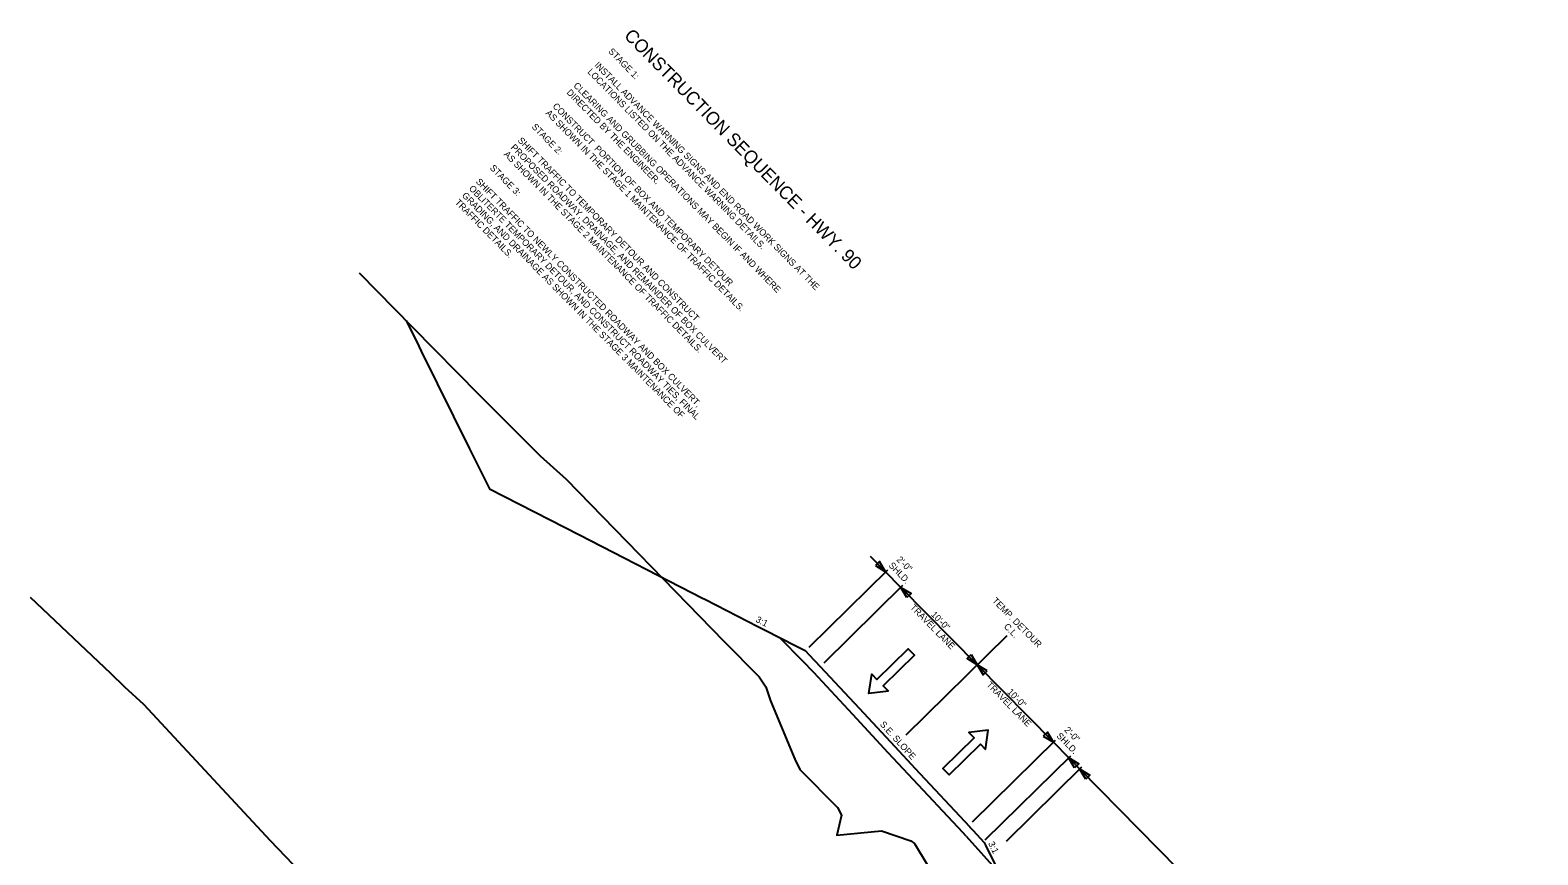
# Model space of a CAD drawing. Extents: x 1660188 to 1660468, y 670370 to 670621.
# Drawn here: x 1660307.3 to 1660446, y 670474.4 to 670550.3 of the extents above; entities that cross this region are included whole.
import ezdxf

# ---------------------------------------------------------------- set-up
doc = ezdxf.new("R2010")
doc.units = 0
for name, color, linetype in [('Default', 7, 'Continuous'), ('R_Annotation', 7, 'Continuous'), ('R_Dimension', 7, 'Continuous'), ('R_Exist Surface', 7, 'Continuous'), ('R_Horz Alg', 7, 'Continuous'), ('R_MOT', 7, 'Continuous')]:
    doc.layers.add(name, color=color, linetype=linetype)

msp = doc.modelspace()

# ---------------------------------------------------------------- linework, layer by layer
at = {"layer": 'Default'}
for points in [[(1660386.24, 670489.44), (1660384.45, 670489.22), (1660384.7, 670491), (1660385.18, 670490.51), (1660388.06, 670493.35), (1660388.64, 670492.76), (1660385.76, 670489.93)], [(1660395.18, 670484.09), (1660395.43, 670485.87), (1660393.64, 670485.65), (1660394.12, 670485.16), (1660391.24, 670482.32), (1660391.82, 670481.74), (1660394.7, 670484.58)]]:
    msp.add_lwpolyline(points, close=True, dxfattribs=at)
at = {"layer": 'R_Dimension'}
for p, q in [((1660378.95, 670493.51), (1660386.17, 670500.61)), ((1660385.98, 670500.43), (1660384.58, 670501.85)), ((1660380.34, 670492.06), (1660387.57, 670499.19)), ((1660387.39, 670499), (1660385.98, 670500.43)), ((1660387.39, 670499), (1660394.4, 670491.88)), ((1660401.42, 670484.75), (1660394.4, 670491.88)), ((1660393.98, 670477.43), (1660401.61, 670484.94)), ((1660401.42, 670484.75), (1660402.82, 670483.33)), ((1660395.15, 670475.77), (1660403.01, 670483.51)), ((1660397.09, 670475.66), (1660404.02, 670482.48)), ((1660402.82, 670483.33), (1660404.23, 670481.9)), ((1660403.83, 670482.3), (1660446, 670439.48))]:
    msp.add_line(p, q, dxfattribs=at)
for points in [[(1660385.05, 670501), (1660385.98, 670500.43), (1660385.43, 670501.37)], [(1660387.94, 670498.07), (1660387.39, 670499), (1660388.32, 670498.44)], [(1660393.85, 670492.82), (1660394.4, 670491.88), (1660393.47, 670492.45)], [(1660395.33, 670491.31), (1660394.4, 670491.88), (1660394.96, 670490.94)], [(1660400.49, 670485.32), (1660401.42, 670484.75), (1660400.87, 670485.69)], [(1660403.37, 670482.39), (1660402.82, 670483.33), (1660403.75, 670482.76)], [(1660404.39, 670481.36), (1660403.83, 670482.3), (1660404.76, 670481.73)]]:
    msp.add_lwpolyline(points, close=True, dxfattribs=at)
at = {"layer": 'R_Exist Surface'}
for points in [[(1660337.55, 670527.94), (1660342.45, 670522.95), (1660348.56, 670516.75), (1660354.2, 670511.1), (1660356.58, 670508.95), (1660371.1, 670494.06), (1660374.33, 670490.78), (1660374.95, 670489.86), (1660375.4, 670488.55), (1660377.62, 670483.18), (1660378.09, 670482.25), (1660381.55, 670478.74), (1660381.91, 670478.03), (1660381.49, 670476.19), (1660385.61, 670476.61), (1660388.29, 670475.69), (1660388.64, 670475.44), (1660389.79, 670473.5)], [(1660307.26, 670498.11), (1660314.65, 670491.11), (1660315.94, 670489.86), (1660317.68, 670488.24), (1660329.34, 670475.72), (1660337.04, 670467.67)]]:
    msp.add_lwpolyline(points, dxfattribs=at)
at = {"layer": 'R_Horz Alg'}
msp.add_line((1660387.87, 670485.44), (1660397.15, 670494.58), dxfattribs=at)
at = {"layer": 'R_MOT'}
for p, q in [((1660378.36, 670492.2), (1660376.26, 670494.36)), ((1660379.36, 670491.16), (1660378.36, 670492.2)), ((1660382.95, 670487.3), (1660379.36, 670491.16)), ((1660386.22, 670483.79), (1660382.95, 670487.3)), ((1660388.1, 670481.77), (1660386.22, 670483.79)), ((1660393.08, 670476.43), (1660388.1, 670481.77)), ((1660393.38, 670476.1), (1660393.08, 670476.43)), ((1660393.38, 670476.1), (1660396.38, 670472.8))]:
    msp.add_line(p, q, dxfattribs=at)
msp.add_lwpolyline([(1660341.85, 670523.57), (1660343.03, 670521.18), (1660343.25, 670520.73), (1660347.7, 670511.76), (1660349.52, 670508.08), (1660357.8, 670503.83), (1660369.14, 670498.01), (1660369.35, 670497.91), (1660370.43, 670497.36), (1660374.22, 670495.41), (1660374.89, 670495.06), (1660377.73, 670493.61), (1660378.57, 670493.18), (1660378.95, 670492.78), (1660379.97, 670491.73), (1660383.56, 670487.87), (1660386.83, 670484.36), (1660388.71, 670482.34), (1660393.69, 670477), (1660393.71, 670476.98), (1660394, 670476.66), (1660395.05, 670475.51), (1660395.17, 670475.27), (1660397, 670471.56)], dxfattribs=at)

# ---------------------------------------------------------------- texts
at = {"layer": 'R_Annotation'}
for s, height, rotation, p in [('CONSTRUCTION SEQUENCE - HWY. 90', 1.2, 314.5576, (1660361.84, 670549.68)), ('STAGE 1: ', 0.6, 314.5576, (1660360.42, 670548.27)), ('LOCATIONS LISTED ON THE ADVANCE WARNING DETAILS. ', 0.6, 314.5576, (1660358.5, 670546.38)), ('INSTALL ADVANCE WARNING SIGNS AND END ROAD WORK SIGNS AT THE ', 0.6, 314.5576, (1660359.14, 670547.01)), ('CLEARING AND GRUBBING OPERATIONS MAY BEGIN IF AND WHERE ', 0.6, 314.5576, (1660357.21, 670545.12)), ('CONSTRUCT  PORTION OF BOX AND TEMPORARY DETOUR', 0.6, 314.5576, (1660355.29, 670543.22)), ('DIRECTED BY THE ENGINEER.', 0.6, 314.5576, (1660356.57, 670544.49)), ('AS SHOWN IN THE STAGE 1 MAINTENANCE OF TRAFFIC DETAILS.', 0.6, 314.5576, (1660354.65, 670542.59)), ('STAGE 2:', 0.6, 314.5576, (1660353.37, 670541.33)), ('PROPOSED ROADWAY, DRAINAGE, AND REMAINDER OF BOX CULVERT', 0.6, 314.5576, (1660351.44, 670539.43)), ('SHIFT TRAFFIC TO TEMPORARY DETOUR AND CONSTRUCT ', 0.6, 314.5576, (1660352.08, 670540.07)), ('AS SHOWN IN THE STAGE 2 MAINTENANCE OF TRAFFIC DETAILS.', 0.6, 314.5576, (1660350.8, 670538.8)), ('SHIFT TRAFFIC TO NEWLY CONSTRUCTED ROADWAY AND BOX CULVERT, ', 0.6, 314.5576, (1660348.23, 670536.28)), ('STAGE 3:', 0.6, 314.5576, (1660349.52, 670537.54)), ('GRADING, AND DRAINAGE AS SHOWN IN THE STAGE 3 MAINTENANCE OF ', 0.6, 314.5576, (1660346.95, 670535.01)), ('OBLITERTE TEMPORARY DETOUR, AND CONSTRUCT ROADWAY TIES, FINAL', 0.6, 314.5576, (1660347.59, 670535.65)), ('TRAFFIC DETAILS.', 0.6, 314.5576, (1660346.31, 670534.38)), ('SHLD.', 0.6, 314.5576, (1660386.21, 670500.97)), ('2\'-0"', 0.6, 314.5576, (1660386.94, 670501.51)), ('TEMP. DETOUR', 0.6, 314.5576, (1660395.74, 670497.72)), ('3:1', 0.6, 333.3952, (1660373.97, 670495.85)), ('TRAVEL LANE', 0.6, 314.5576, (1660388.19, 670497.11)), ('10\'-0"', 0.6, 314.5576, (1660390.11, 670496.45)), ('C.L.', 0.6, 314.5576, (1660396.81, 670495.34)), ('TRAVEL LANE', 0.6, 314.5576, (1660395.21, 670489.99)), ('10\'-0"', 0.6, 314.5576, (1660397.13, 670489.33)), ('S.E. SLOPE', 0.6, 312.322, (1660385.41, 670486.36)), ('SHLD.', 0.6, 314.5576, (1660401.65, 670485.29)), ('2\'-0"', 0.6, 314.5576, (1660402.37, 670485.84)), ('3:1', 0.6, 295.7201, (1660395.4, 670475.45))]:
    msp.add_text(s, height=height, rotation=rotation, dxfattribs=at).set_placement(p)

doc.saveas('drawing.dxf')
